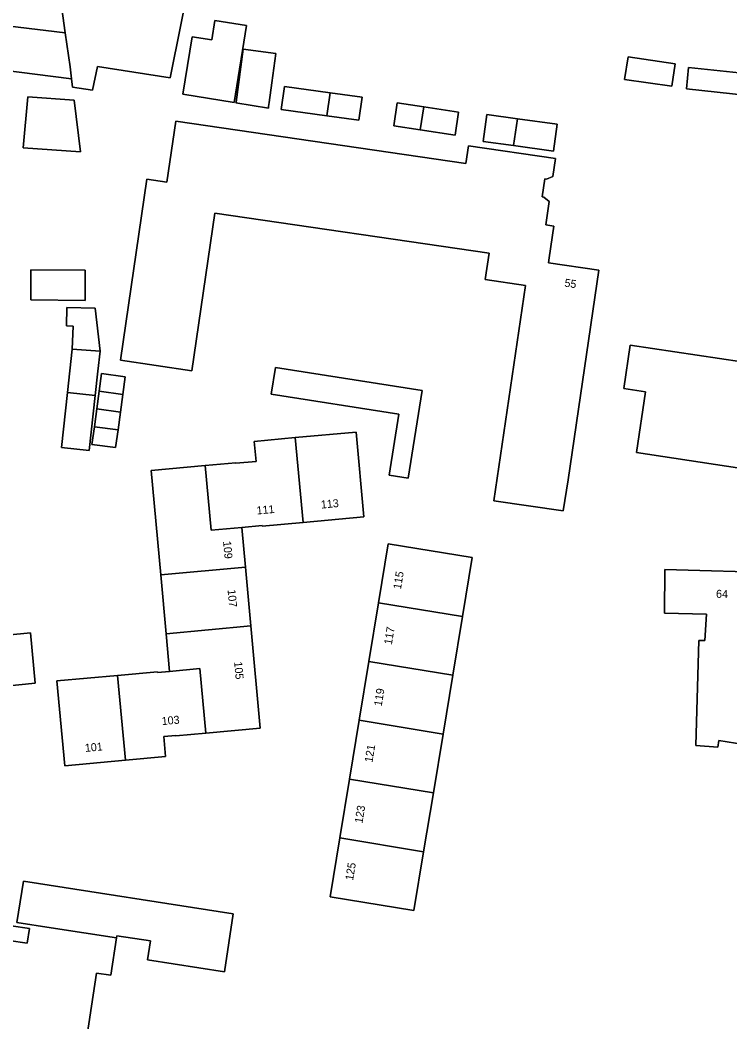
# Model space of a CAD drawing. Extents: x 163008 to 163854, y 382777 to 383982.
# Drawn here: x 163408.4 to 163497.1, y 383282.1 to 383407.3 of the extents above; entities that cross this region are included whole.
import ezdxf

# ---------------------------------------------------------------- set-up
doc = ezdxf.new("R2010")
doc.units = 0
for name, color, linetype in [('IMGEO_Erf', 7, 'Continuous'), ('IMGEO_Pand', 7, 'Continuous'), ('IMGEO_Pand_nummerreeks', 7, 'Continuous')]:
    doc.layers.add(name, color=color, linetype=linetype)

msp = doc.modelspace()

# ---------------------------------------------------------------- linework, layer by layer
at = {"layer": 'IMGEO_Erf'}
for points in [[(163431.21, 383419.96), (163427.19, 383400.04), (163418.12, 383401.46), (163417.5, 383398.48), (163414.99, 383398.87), (163414.86, 383399.91), (163406.03, 383401.03)], [(163396.64, 383407.98), (163395.97, 383402.36), (163398.55, 383402.05), (163398.41, 383400.93), (163403.95, 383400.27), (163404.04, 383401.03), (163404.72, 383406.78), (163414.09, 383405.66), (163412.66, 383416.04)], [(163500, 383351.05), (163485.45, 383353.23), (163486.59, 383360.83), (163483.86, 383361.24), (163484.68, 383366.66), (163498.62, 383364.57)], [(163392.37, 383328.99), (163409.73, 383330.72), (163410.34, 383324.41), (163393.2, 383322.69)], [(163408.04, 383294.55), (163408.85, 383299.69), (163435.08, 383295.6), (163433.96, 383288.36), (163424.36, 383289.85), (163424.72, 383292.24), (163420.52, 383292.87), (163420.48, 383292.6), (163419.78, 383287.93), (163418, 383288.2), (163414.63, 383265.91)], [(163407.04, 383292.29), (163409.33, 383291.95), (163409.6, 383293.78), (163407.32, 383294.12)]]:
    msp.add_lwpolyline(points, dxfattribs=at)
for points in [[(163428.76, 383397.99), (163429.93, 383405.18), (163432.4, 383404.78), (163432.79, 383407.22), (163436.74, 383406.58), (163435.17, 383396.95)], [(163435.4, 383396.91), (163435.42, 383397.01), (163436.33, 383403.64), (163440.4, 383403.08), (163439.9, 383399.43), (163439.56, 383396.94), (163439.49, 383396.45), (163439.46, 383396.25)], [(163483.98, 383399.83), (163484.4, 383402.67), (163490.3, 383401.81), (163489.88, 383399)], [(163491.69, 383398.67), (163491.98, 383401.33), (163499.87, 383400.48), (163499.58, 383397.81), (163499.36, 383397.84)], [(163446.77, 383395.31), (163441.06, 383396.1), (163441.46, 383398.97), (163447.2, 383398.18), (163451.18, 383397.62), (163450.78, 383394.75)], [(163408.84, 383391.31), (163409.42, 383397.67), (163415.19, 383397.26), (163415.98, 383390.8)], [(163455.14, 383394.05), (163455.55, 383396.93), (163458.87, 383396.42), (163463.2, 383395.75), (163462.8, 383392.87), (163458.44, 383393.54)], [(163432.77, 383383.15), (163429.88, 383363.46), (163420.97, 383364.76), (163424.28, 383387.39), (163426.79, 383387.02), (163427.9, 383394.62), (163464.15, 383389.32), (163464.47, 383391.54), (163475.33, 383389.95), (163475.01, 383387.7), (163474.22, 383387.38), (163474.01, 383387.41), (163473.68, 383385.18), (163473.89, 383385.14), (163474.55, 383384.61), (163474.12, 383381.68), (163475.15, 383381.53), (163474.56, 383377.56), (163474.47, 383376.93), (163480.76, 383376.01), (163476.92, 383349.82), (163476.31, 383345.94), (163467.65, 383347.21), (163471.59, 383374.12), (163466.57, 383374.86), (163467.05, 383378.13)], [(163466.29, 383392.09), (163466.74, 383395.45), (163470.58, 383394.93), (163475.54, 383394.26), (163475.08, 383390.89), (163470.08, 383391.57)], [(163409.77, 383372.29), (163409.77, 383376.06), (163416.59, 383376.02), (163416.59, 383372.21)], [(163418.15, 383363.4), (163417.8, 383360.37), (163417.05, 383353.48), (163413.61, 383353.86), (163414.36, 383360.74), (163414.95, 383366.15), (163415.06, 383369.01), (163414.23, 383369.07), (163414.29, 383371.35), (163417.83, 383371.25), (163418.45, 383365.9)], [(163420.98, 383358.28), (163420.68, 383356.06), (163420.38, 383353.85), (163417.42, 383354.25), (163417.72, 383356.46), (163418.02, 383358.68), (163418.32, 383360.89), (163418.61, 383363.1), (163421.58, 383362.7), (163421.28, 383360.49)], [(163439.83, 383360.54), (163440.36, 383363.86), (163458.68, 383360.97), (163456.95, 383350.03), (163454.55, 383350.41), (163455.75, 383358.03)], [(163437.28, 383331.58), (163438.45, 383318.8), (163431.63, 383318.17), (163427.89, 383317.83), (163427.88, 383317.9), (163426.38, 383317.76), (163426.61, 383315.26), (163421.59, 383314.79), (163414.01, 383314.09), (163413.03, 383324.7), (163420.62, 383325.38), (163425.6, 383325.83), (163425.6, 383325.75), (163427.1, 383325.9), (163426.68, 383330.6), (163426.01, 383337.96), (163424.83, 383350.99), (163431.58, 383351.6), (163435.38, 383351.95), (163435.39, 383351.89), (163437.92, 383352.12), (163437.68, 383354.63), (163442.81, 383355.1), (163450.42, 383355.8), (163451.4, 383345.21), (163443.79, 383344.51), (163438.69, 383344.04), (163438.68, 383344.11), (163436.16, 383343.87), (163436.61, 383338.93)], [(163447.18, 383297.74), (163448.39, 383305.09), (163449.6, 383312.44), (163450.81, 383319.79), (163452.02, 383327.13), (163453.23, 383334.48), (163454.44, 383341.83), (163464.93, 383340.14), (163463.71, 383332.75), (163462.5, 383325.41), (163461.29, 383318.06), (163460.08, 383310.71), (163458.86, 383303.36), (163457.65, 383296.03)], [(163495.77, 383317.26), (163495.64, 383316.44), (163492.86, 383316.62), (163493.24, 383329.74), (163494, 383329.76), (163494.21, 383333.03), (163488.96, 383333.16), (163489.01, 383338.63), (163503.62, 383338.21), (163503.57, 383336.25), (163504.14, 383336.16), (163503.95, 383331.81), (163506.18, 383331.46), (163506.4, 383332.87), (163512.37, 383331.94), (163511.28, 383325), (163512.16, 383324.86), (163510.62, 383314.98), (163503.63, 383316.07), (163503.75, 383316.82), (163502.12, 383317.07), (163501.99, 383316.28)]]:
    msp.add_lwpolyline(points, close=True, dxfattribs=at)
at = {"layer": 'IMGEO_Pand'}
for points in [[(163431.21, 383419.96), (163422.21, 383421.32), (163422.81, 383424.2), (163431.81, 383422.57), (163433.28, 383430.69), (163415.38, 383433.94), (163414.45, 383428.8), (163413.84, 383425.43), (163412.63, 383418.74), (163412.44, 383417.67), (163412.66, 383416.04), (163414.09, 383405.66), (163414.68, 383401.43), (163414.86, 383399.91), (163414.99, 383398.87), (163417.5, 383398.48), (163418.12, 383401.46), (163427.19, 383400.04)], [(163428.76, 383397.99), (163435.17, 383396.95), (163436.74, 383406.58), (163432.79, 383407.22), (163432.4, 383404.78), (163429.93, 383405.18)], [(163414.09, 383405.66), (163404.72, 383406.78), (163404.04, 383401.03), (163403.95, 383400.27), (163405.91, 383400.04), (163406.03, 383401.03), (163414.86, 383399.91), (163414.68, 383401.43)], [(163435.4, 383396.91), (163439.46, 383396.25), (163439.49, 383396.45), (163439.56, 383396.94), (163439.9, 383399.43), (163440.4, 383403.08), (163436.33, 383403.64), (163435.42, 383397.01)], [(163483.98, 383399.83), (163489.88, 383399), (163490.3, 383401.81), (163484.4, 383402.67)], [(163499.36, 383397.84), (163499.58, 383397.81), (163499.87, 383400.48), (163491.98, 383401.33), (163491.69, 383398.67)], [(163447.2, 383398.18), (163441.46, 383398.97), (163441.06, 383396.1), (163446.77, 383395.31)], [(163447.2, 383398.18), (163446.77, 383395.31), (163450.78, 383394.75), (163451.18, 383397.62)], [(163415.19, 383397.26), (163409.42, 383397.67), (163408.84, 383391.31), (163415.98, 383390.8)], [(163458.87, 383396.42), (163455.55, 383396.93), (163455.14, 383394.05), (163458.44, 383393.54)], [(163458.87, 383396.42), (163458.44, 383393.54), (163462.8, 383392.87), (163463.2, 383395.75)], [(163474.56, 383377.56), (163475.15, 383381.53), (163474.12, 383381.68), (163474.55, 383384.61), (163473.89, 383385.14), (163473.68, 383385.18), (163474.01, 383387.41), (163474.22, 383387.38), (163475.01, 383387.7), (163475.33, 383389.95), (163464.47, 383391.54), (163464.15, 383389.32), (163427.9, 383394.62), (163426.79, 383387.02), (163424.28, 383387.39), (163420.97, 383364.76), (163429.88, 383363.46), (163432.77, 383383.15), (163467.05, 383378.13), (163466.57, 383374.86), (163471.59, 383374.12), (163467.65, 383347.21), (163476.31, 383345.94), (163476.92, 383349.82), (163480.76, 383376.01), (163474.47, 383376.93)], [(163470.58, 383394.93), (163466.74, 383395.45), (163466.29, 383392.09), (163470.08, 383391.57)], [(163470.58, 383394.93), (163470.08, 383391.57), (163475.08, 383390.89), (163475.54, 383394.26)], [(163409.77, 383376.06), (163409.77, 383372.29), (163416.59, 383372.21), (163416.59, 383376.02)], [(163414.95, 383366.15), (163418.45, 383365.9), (163417.83, 383371.25), (163414.29, 383371.35), (163414.23, 383369.07), (163415.06, 383369.01)], [(163418.45, 383365.9), (163414.95, 383366.15), (163414.36, 383360.74), (163417.8, 383360.37), (163418.15, 383363.4)], [(163421.58, 383362.7), (163418.61, 383363.1), (163418.32, 383360.89), (163421.28, 383360.49)], [(163458.68, 383360.97), (163440.36, 383363.86), (163439.83, 383360.54), (163455.75, 383358.03), (163454.55, 383350.41), (163456.95, 383350.03)], [(163417.8, 383360.37), (163414.36, 383360.74), (163413.61, 383353.86), (163417.05, 383353.48)], [(163421.28, 383360.49), (163418.32, 383360.89), (163418.02, 383358.68), (163420.98, 383358.28)], [(163420.98, 383358.28), (163418.02, 383358.68), (163417.72, 383356.46), (163420.68, 383356.06)], [(163420.68, 383356.06), (163417.72, 383356.46), (163417.42, 383354.25), (163420.38, 383353.85)], [(163450.42, 383355.8), (163442.81, 383355.1), (163443.79, 383344.51), (163451.4, 383345.21)], [(163442.81, 383355.1), (163437.68, 383354.63), (163437.92, 383352.12), (163435.39, 383351.89), (163435.38, 383351.95), (163431.58, 383351.6), (163432.32, 383343.52), (163436.16, 383343.87), (163438.68, 383344.11), (163438.69, 383344.04), (163443.79, 383344.51)], [(163436.16, 383343.87), (163432.32, 383343.52), (163431.58, 383351.6), (163424.83, 383350.99), (163426.01, 383337.96), (163436.61, 383338.93)], [(163464.93, 383340.14), (163454.44, 383341.83), (163453.23, 383334.48), (163463.71, 383332.75)], [(163436.61, 383338.93), (163426.01, 383337.96), (163426.68, 383330.6), (163437.28, 383331.58)], [(163510.62, 383314.98), (163512.16, 383324.86), (163511.28, 383325), (163512.37, 383331.94), (163506.4, 383332.87), (163506.18, 383331.46), (163503.95, 383331.81), (163504.14, 383336.16), (163503.57, 383336.25), (163503.62, 383338.21), (163489.01, 383338.63), (163488.96, 383333.16), (163494.21, 383333.03), (163494, 383329.76), (163493.24, 383329.74), (163492.86, 383316.62), (163495.64, 383316.44), (163495.77, 383317.26), (163501.99, 383316.28), (163502.12, 383317.07), (163503.75, 383316.82), (163503.63, 383316.07)], [(163463.71, 383332.75), (163453.23, 383334.48), (163452.02, 383327.13), (163462.5, 383325.41)], [(163437.28, 383331.58), (163426.68, 383330.6), (163427.1, 383325.9), (163430.89, 383326.24), (163431.63, 383318.17), (163438.45, 383318.8)], [(163462.5, 383325.41), (163452.02, 383327.13), (163450.81, 383319.79), (163461.29, 383318.06)], [(163430.89, 383326.24), (163427.1, 383325.9), (163425.6, 383325.75), (163425.6, 383325.83), (163420.62, 383325.38), (163421.59, 383314.79), (163426.61, 383315.26), (163426.38, 383317.76), (163427.88, 383317.9), (163427.89, 383317.83), (163431.63, 383318.17)], [(163420.62, 383325.38), (163413.03, 383324.7), (163414.01, 383314.09), (163421.59, 383314.79)], [(163461.29, 383318.06), (163450.81, 383319.79), (163449.6, 383312.44), (163460.08, 383310.71)], [(163460.08, 383310.71), (163449.6, 383312.44), (163448.39, 383305.09), (163458.86, 383303.36)], [(163458.86, 383303.36), (163448.39, 383305.09), (163447.18, 383297.74), (163457.65, 383296.03)], [(163435.08, 383295.6), (163408.85, 383299.69), (163408.04, 383294.55), (163412.33, 383293.88), (163420.48, 383292.6), (163420.52, 383292.87), (163424.72, 383292.24), (163424.36, 383289.85), (163433.96, 383288.36)]]:
    msp.add_lwpolyline(points, close=True, dxfattribs=at)
for points in [[(163498.62, 383364.57), (163484.68, 383366.66), (163483.86, 383361.24), (163486.59, 383360.83), (163485.45, 383353.23), (163500, 383351.05)], [(163393.2, 383322.69), (163410.34, 383324.41), (163409.73, 383330.72), (163392.37, 383328.99)], [(163414.63, 383265.91), (163418, 383288.2), (163419.78, 383287.93), (163420.48, 383292.6), (163412.33, 383293.88), (163408.04, 383294.55)], [(163407.32, 383294.12), (163409.6, 383293.78), (163409.33, 383291.95), (163407.04, 383292.29)]]:
    msp.add_lwpolyline(points, dxfattribs=at)

# ---------------------------------------------------------------- texts
at = {"layer": 'IMGEO_Pand_nummerreeks'}
for s, rotation, p in [('55', 351.6807, (163476.41, 383373.97)), ('113', 5.254, (163446.07, 383346.23)), ('111', 5.254, (163438.04, 383345.49)), ('109', 275.2252, (163433.8, 383342.14)), ('115', 80.6438, (163456.03, 383336.1)), ('107', 275.2252, (163434.36, 383336.09)), ('64', 358.2337, (163495.39, 383335.1)), ('117', 80.6438, (163454.89, 383329.18)), ('105', 275.2252, (163435.18, 383327.08)), ('119', 80.6438, (163453.62, 383321.49)), ('103', 5.2712, (163426.18, 383319.18)), ('101', 5.3056, (163416.58, 383315.83)), ('121', 80.6438, (163452.46, 383314.47)), ('123', 80.6438, (163451.21, 383306.87)), ('125', 80.6438, (163450.04, 383299.73))]:
    msp.add_text(s, height=1, rotation=rotation, dxfattribs=at).set_placement(p)

doc.saveas('drawing.dxf')
